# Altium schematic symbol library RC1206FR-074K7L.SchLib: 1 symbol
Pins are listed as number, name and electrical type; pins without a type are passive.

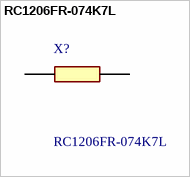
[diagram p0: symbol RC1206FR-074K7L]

## RC1206FR-074K7L
designator X?
Yageo 4.7k, 1206 (3216M) Thick Film SMD Resistor +/-1% 0.5 W, 0.25 W - RC1206FR-074K7L; Geometry.Height: 0.65mm
footprint RESC3116X65N
pins: 1, 2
